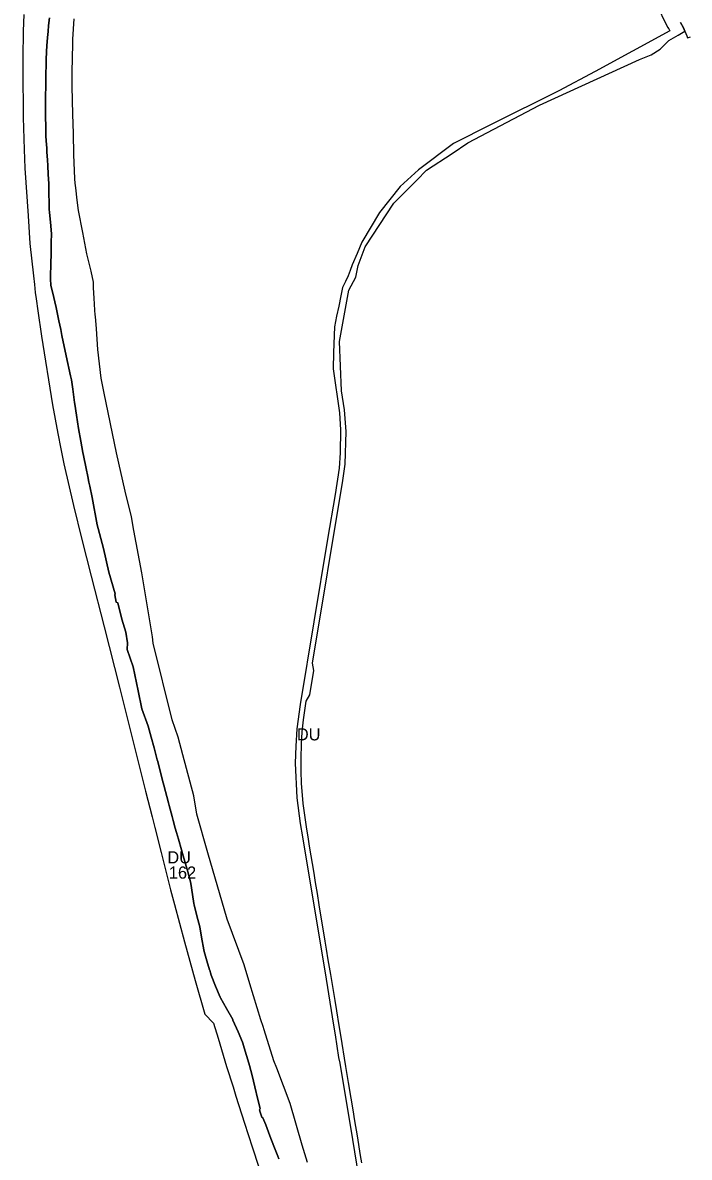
# Model space of a CAD drawing. Extents: x -521047 to -518054, y -1194945 to -1189555.
# Drawn here: x -520854 to -520307, y -1191621 to -1190690 of the extents above; entities that cross this region are included whole.
import ezdxf

# ---------------------------------------------------------------- set-up
doc = ezdxf.new("R2010")
doc.units = 0
for name, color, linetype in [('90310013', 7, 'Continuous'), ('90310023', 7, 'Continuous'), ('90320013', 7, 'Continuous'), ('ID_navrh', 7, 'Continuous')]:
    doc.layers.add(name, color=color, linetype=linetype)

msp = doc.modelspace()

# ---------------------------------------------------------------- linework, layer by layer
at = {"layer": '90310013'}
for points in [[(-520334, -1190674.28), (-520324.46, -1190693.89), (-520323.5, -1190695.35), (-520322.54, -1190696.8), (-520383.85, -1190730.39), (-520413.62, -1190746.07), (-520469.27, -1190773.73), (-520500.11, -1190789.41), (-520528.99, -1190810.95), (-520544.03, -1190824.72), (-520560.86, -1190845.88), (-520575.39, -1190870.36), (-520579.33, -1190879.67), (-520583.27, -1190888.97), (-520584.97, -1190893.45), (-520586.68, -1190897.92), (-520588.94, -1190902.65), (-520591.21, -1190907.38), (-520592.68, -1190914.39), (-520594.41, -1190922.81), (-520596.29, -1190931.07), (-520597.97, -1190939.69), (-520598.61, -1190960.68), (-520598.93, -1190974.08), (-520593.81, -1191010.23), (-520592.99, -1191024.28), (-520593.17, -1191043.04), (-520594.04, -1191055.69), (-520597.48, -1191077.12), (-520603.55, -1191113.81), (-520626.01, -1191249.41), (-520628.76, -1191269.45), (-520629.76, -1191283.58), (-520630.1, -1191297.74), (-520628.78, -1191326.02), (-520625.98, -1191347.07), (-520624.05, -1191357.94), (-520604.82, -1191474.76), (-520598.71, -1191512.42), (-520597.37, -1191520.53), (-520594.55, -1191539), (-520593.47, -1191543.67), (-520583.24, -1191606.18), (-520572.92, -1191668.76)], [(-520575.51, -1191625.38), (-520576.48, -1191619.53), (-520579.1, -1191603.39), (-520581.19, -1191591.03), (-520582.68, -1191582), (-520584.24, -1191572.29), (-520586.36, -1191559.62), (-520588.55, -1191546.35), (-520592.74, -1191520.81), (-520594.1, -1191512.73), (-520596.04, -1191500.86), (-520597.47, -1191492.24), (-520599.4, -1191480.74), (-520601.01, -1191470.86), (-520603, -1191458.86), (-520604.41, -1191450.26), (-520605.54, -1191443.5), (-520610.43, -1191413.76), (-520611.93, -1191404.62), (-520613.42, -1191395.5), (-520614.72, -1191387.87), (-520618.35, -1191365.76), (-520619.6, -1191358.04), (-520620.71, -1191351.68), (-520623.65, -1191330.68), (-520625.07, -1191313.94), (-520625.36, -1191304.16), (-520625.38, -1191293.53), (-520625.11, -1191281.97), (-520624.38, -1191271.96), (-520623.25, -1191261.94), (-520621.13, -1191246.77), (-520618.19, -1191241.45), (-520614.89, -1191221.55), (-520615.94, -1191215.64), (-520591.05, -1191065.64), (-520589.24, -1191052.36), (-520588.39, -1191025.58), (-520589.79, -1191007.77), (-520592.04, -1190992.31), (-520593.76, -1190951.86), (-520586.27, -1190909.59), (-520580.44, -1190899.06), (-520578.54, -1190889.51), (-520572.63, -1190874.12), (-520549.3, -1190838.28), (-520530.27, -1190819.39), (-520522.25, -1190811.26), (-520501.34, -1190797.6), (-520488.55, -1190788.82), (-520429.7, -1190757.81), (-520347.53, -1190720.51), (-520337.94, -1190716.53), (-520330.69, -1190711.95), (-520323.58, -1190704.71), (-520315.88, -1190700.41), (-520310.32, -1190697.3), (-520311.54, -1190694.38), (-520313.81, -1190690.05)]]:
    msp.add_lwpolyline(points, dxfattribs=at)
at = {"layer": '90310023'}
for points in [[(-520852.94, -1190683.51), (-520853.37, -1190697.08), (-520853.44, -1190702.35), (-520853.63, -1190713.88), (-520853.79, -1190723.11), (-520853.87, -1190735.1), (-520853.81, -1190743.83), (-520853.6, -1190752.22), (-520853.48, -1190767.88), (-520852.66, -1190794.34), (-520852.06, -1190809.58), (-520849.49, -1190848.58), (-520847.98, -1190871.46), (-520845.07, -1190897.78), (-520844.23, -1190905.1), (-520843.48, -1190911.63), (-520842.9, -1190916.64), (-520841.49, -1190926.47), (-520838.45, -1190947.47), (-520829.51, -1191003.76), (-520825.08, -1191027.11), (-520822.58, -1191039.85), (-520820.01, -1191052.05), (-520812.23, -1191086.24), (-520805.2, -1191114.16), (-520797.61, -1191144.17), (-520786.96, -1191185.86), (-520774.39, -1191235.28), (-520762.01, -1191284.51), (-520752.93, -1191320.48), (-520747.53, -1191341.72), (-520745.31, -1191350.43), (-520740.08, -1191370.95), (-520732.39, -1191401.49), (-520729.17, -1191413.61), (-520721.14, -1191444.12), (-520712.23, -1191475.88), (-520704.46, -1191503.52), (-520697.13, -1191510.79), (-520693.46, -1191523.23), (-520686.61, -1191546.52), (-520681.21, -1191563.06), (-520678.86, -1191570.86), (-520671.8, -1191593.01), (-520668.87, -1191602.22), (-520665.33, -1191613.04), (-520660.4, -1191628.12)], [(-520643.73, -1191622.06), (-520644.52, -1191620), (-520647.71, -1191611.67), (-520650.9, -1191603.35), (-520654.37, -1191594.38), (-520656.67, -1191588.4), (-520657.54, -1191587.89), (-520658.88, -1191583.95), (-520659.53, -1191582.02), (-520659, -1191580.96), (-520660.82, -1191573.42), (-520663.33, -1191563.05), (-520665.57, -1191553.76), (-520667.57, -1191545.47), (-520668.09, -1191543.82), (-520672, -1191531.21), (-520673.22, -1191527.27), (-520673.5, -1191526.37), (-520677.1, -1191518.04), (-520681.26, -1191508.41), (-520681.46, -1191507.94), (-520686.56, -1191498.88), (-520691.48, -1191490.13), (-520691.77, -1191489.43), (-520695.45, -1191480.44), (-520699.15, -1191471.42), (-520699.7, -1191469.55), (-520700.29, -1191467.53), (-520700.44, -1191467.02), (-520702.59, -1191459.74), (-520704.85, -1191452.06), (-520705.09, -1191450.73), (-520707.01, -1191440.35), (-520707.04, -1191440.19), (-520708.5, -1191432.23), (-520708.55, -1191432.06), (-520708.58, -1191431.92), (-520710.82, -1191422.94), (-520713.09, -1191413.86), (-520713.37, -1191412.72), (-520714.5, -1191405.34), (-520715.9, -1191396.27), (-520716.12, -1191394.83), (-520718.38, -1191386.7), (-520720.76, -1191378.14), (-520722.03, -1191373.58), (-520723.44, -1191368.78), (-520726.04, -1191360.01), (-520727.71, -1191354.35), (-520728.59, -1191350.94), (-520730.21, -1191344.64), (-520731.14, -1191341.3), (-520733.65, -1191332.34), (-520734.26, -1191330.16), (-520738.06, -1191315.61), (-520738.56, -1191313.65), (-520741, -1191304.12), (-520743.03, -1191296.2), (-520743.4, -1191294.83), (-520746.06, -1191284.98), (-520748.41, -1191276.25), (-520750.85, -1191267.23), (-520755.98, -1191253.01), (-520759.01, -1191238.19), (-520763.23, -1191218.65), (-520768, -1191204.35), (-520767.93, -1191199.01), (-520769.22, -1191190.15), (-520772.34, -1191179.58), (-520775.88, -1191166.14), (-520777.03, -1191165.48), (-520778.32, -1191159.41), (-520777.9, -1191158.6), (-520783.01, -1191140.89), (-520787.55, -1191121.39), (-520791.94, -1191104.99), (-520792.74, -1191102), (-520796.93, -1191079.59), (-520798.81, -1191070.46), (-520799.51, -1191067.05), (-520800.44, -1191062.53), (-520801.76, -1191055.91), (-520803.88, -1191045.24), (-520804.36, -1191042.81), (-520806.03, -1191033.62), (-520807.96, -1191023.01), (-520809.71, -1191012.14), (-520811.15, -1191003.13), (-520811.34, -1191001.73), (-520812.78, -1190990.94), (-520813.82, -1190983.19), (-520814.56, -1190979.91), (-520818.22, -1190963.51), (-520821.62, -1190946.91), (-520821.98, -1190945.15), (-520822.65, -1190941.82), (-520824.09, -1190934.71), (-520824.34, -1190933.44), (-520826.26, -1190923.93), (-520829.46, -1190910.89), (-520830.74, -1190905.71), (-520831.08, -1190900.46), (-520831.02, -1190897.74), (-520830.82, -1190888.52), (-520830.61, -1190878.92), (-520830.42, -1190870.43), (-520830.27, -1190863.43), (-520831.11, -1190853.75), (-520831.79, -1190846.02), (-520832.02, -1190843.31), (-520832.12, -1190838.18), (-520832.28, -1190829.94), (-520832.41, -1190823.17), (-520832.46, -1190822.22), (-520832.83, -1190814.81), (-520833.2, -1190807.31), (-520833.41, -1190803.07), (-520833.68, -1190799.5), (-520833.91, -1190796.45), (-520834.16, -1190793.02), (-520834.61, -1190787.07), (-520834.92, -1190782.92), (-520834.94, -1190780.45), (-520834.99, -1190774.65), (-520835.04, -1190768.27), (-520835.08, -1190762.76), (-520835.08, -1190762.45), (-520835.08, -1190762.16), (-520835.05, -1190756.12), (-520835.02, -1190749.26), (-520834.99, -1190743.76), (-520834.99, -1190742.61), (-520834.91, -1190737.42), (-520834.82, -1190731.68), (-520834.72, -1190725.53), (-520834.67, -1190722.46), (-520834.57, -1190720.65), (-520834.19, -1190713.84), (-520833.93, -1190709.32), (-520833.53, -1190702.3), (-520833.06, -1190697.52), (-520832.56, -1190692.51), (-520831.92, -1190686.11)]]:
    msp.add_lwpolyline(points, dxfattribs=at)
at = {"layer": '90320013'}
for points in [[(-520831.92, -1190686.11), (-520832.56, -1190692.51), (-520833.06, -1190697.52), (-520833.53, -1190702.3), (-520833.93, -1190709.32), (-520834.19, -1190713.84), (-520834.57, -1190720.65), (-520834.67, -1190722.46), (-520834.72, -1190725.53), (-520834.82, -1190731.68), (-520834.91, -1190737.42), (-520834.99, -1190742.61), (-520834.99, -1190743.76), (-520835.02, -1190749.26), (-520835.05, -1190756.12), (-520835.08, -1190762.16), (-520835.08, -1190762.45), (-520835.08, -1190762.76), (-520835.04, -1190768.27), (-520834.99, -1190774.65), (-520834.94, -1190780.45), (-520834.92, -1190782.92), (-520834.61, -1190787.07), (-520834.16, -1190793.02), (-520833.91, -1190796.45), (-520833.68, -1190799.5), (-520833.41, -1190803.07), (-520833.2, -1190807.31), (-520832.83, -1190814.81), (-520832.46, -1190822.22), (-520832.41, -1190823.17), (-520832.28, -1190829.94), (-520832.12, -1190838.18), (-520832.02, -1190843.31), (-520831.79, -1190846.02), (-520831.11, -1190853.75), (-520830.27, -1190863.43), (-520830.42, -1190870.43), (-520830.61, -1190878.92), (-520830.82, -1190888.52), (-520831.02, -1190897.74), (-520831.08, -1190900.46), (-520830.74, -1190905.71), (-520829.46, -1190910.89), (-520826.26, -1190923.93), (-520824.34, -1190933.44), (-520824.09, -1190934.71), (-520822.65, -1190941.82), (-520821.98, -1190945.15), (-520821.62, -1190946.91), (-520818.22, -1190963.51), (-520814.56, -1190979.91), (-520813.82, -1190983.19), (-520812.78, -1190990.94), (-520811.34, -1191001.73), (-520811.15, -1191003.13), (-520809.71, -1191012.14), (-520807.96, -1191023.01), (-520806.03, -1191033.62), (-520804.36, -1191042.81), (-520803.88, -1191045.24), (-520801.76, -1191055.91), (-520800.44, -1191062.53), (-520799.51, -1191067.05), (-520798.81, -1191070.46), (-520796.93, -1191079.59), (-520792.74, -1191102), (-520791.94, -1191104.99), (-520787.55, -1191121.39), (-520783.01, -1191140.89), (-520777.9, -1191158.6), (-520778.32, -1191159.41), (-520777.03, -1191165.48), (-520775.88, -1191166.14), (-520772.34, -1191179.58), (-520769.22, -1191190.15), (-520767.93, -1191199.01), (-520768, -1191204.35), (-520763.23, -1191218.65), (-520759.01, -1191238.19), (-520755.98, -1191253.01), (-520750.85, -1191267.23), (-520748.41, -1191276.25), (-520746.06, -1191284.98), (-520743.4, -1191294.83), (-520743.03, -1191296.2), (-520741, -1191304.12), (-520738.56, -1191313.65), (-520738.06, -1191315.61), (-520734.26, -1191330.16), (-520733.65, -1191332.34), (-520731.14, -1191341.3), (-520730.21, -1191344.64), (-520728.59, -1191350.94), (-520727.71, -1191354.35), (-520726.04, -1191360.01), (-520723.44, -1191368.78), (-520722.03, -1191373.58), (-520720.76, -1191378.14), (-520718.38, -1191386.7), (-520716.12, -1191394.83), (-520715.9, -1191396.27), (-520714.5, -1191405.34), (-520713.37, -1191412.72), (-520713.09, -1191413.86), (-520710.82, -1191422.94), (-520708.58, -1191431.92), (-520708.55, -1191432.06), (-520708.5, -1191432.23), (-520707.04, -1191440.19), (-520707.01, -1191440.35), (-520705.09, -1191450.73), (-520704.85, -1191452.06), (-520702.59, -1191459.74), (-520700.44, -1191467.02), (-520700.29, -1191467.53), (-520699.7, -1191469.55), (-520699.15, -1191471.42), (-520695.45, -1191480.44), (-520691.77, -1191489.43), (-520691.48, -1191490.13), (-520686.56, -1191498.88), (-520681.46, -1191507.94), (-520681.26, -1191508.41), (-520677.1, -1191518.04), (-520673.5, -1191526.37), (-520673.22, -1191527.27), (-520672, -1191531.21), (-520668.09, -1191543.82), (-520667.57, -1191545.47), (-520665.57, -1191553.76), (-520663.33, -1191563.05), (-520660.82, -1191573.42), (-520659, -1191580.96), (-520659.53, -1191582.02), (-520658.88, -1191583.95), (-520657.54, -1191587.89), (-520656.67, -1191588.4), (-520654.37, -1191594.38), (-520650.9, -1191603.35), (-520647.71, -1191611.67), (-520644.52, -1191620), (-520643.73, -1191622.06)], [(-520620.11, -1191625.25), (-520624.44, -1191610.86), (-520634.42, -1191576.76), (-520645.29, -1191547.71), (-520647.74, -1191541.74), (-520655.62, -1191516.43), (-520656.53, -1191513.73), (-520658.4, -1191508.21), (-520667.4, -1191478.56), (-520672.11, -1191463.11), (-520686.01, -1191425.6), (-520701.83, -1191371.04), (-520710.85, -1191339.33), (-520713.4, -1191324.5), (-520722.32, -1191290.79), (-520726.33, -1191276.25), (-520728.77, -1191269.08), (-520731.29, -1191262.08), (-520746.79, -1191199.07), (-520747.26, -1191194.03), (-520756.19, -1191141.57), (-520762.68, -1191106.73), (-520764.59, -1191095.68), (-520769.65, -1191074.63), (-520776.73, -1191043.11), (-520787.08, -1190994.15), (-520789.33, -1190981.89), (-520792.16, -1190958.16), (-520793.22, -1190941.3), (-520794.11, -1190931.35), (-520794.23, -1190929.98), (-520794.58, -1190926.05), (-520795.25, -1190916.18), (-520795.63, -1190907.7), (-520795.84, -1190903.04), (-520796.83, -1190897.77), (-520797.4, -1190895.45), (-520797.73, -1190894.1), (-520801.14, -1190879.93), (-520804.62, -1190862.21), (-520808.06, -1190844.37), (-520809.15, -1190835.67), (-520810.29, -1190825.6), (-520810.72, -1190821.89), (-520810.92, -1190818.26), (-520811.77, -1190798.26), (-520812.06, -1190781.24), (-520812.68, -1190765.38), (-520813.33, -1190742.53), (-520813.31, -1190730.65), (-520812.83, -1190707.72), (-520812.74, -1190703.8), (-520811.58, -1190686.99)], [(-520313.81, -1190690.05), (-520311.54, -1190694.38), (-520310.32, -1190697.3), (-520308.79, -1190700.97), (-520308.05, -1190702.75), (-520305.81, -1190701.95)]]:
    msp.add_lwpolyline(points, dxfattribs=at)

# ---------------------------------------------------------------- texts
at = {"layer": '90310013'}
msp.add_text('DU', height=10, rotation=360, dxfattribs=at).set_placement((-520628.77, -1191278.95))
at = {"layer": '90310023'}
msp.add_text('DU', height=10, rotation=0, dxfattribs=at).set_placement((-520735.07, -1191379.83))
at = {"layer": 'ID_navrh'}
msp.add_text('162', height=10, rotation=0, dxfattribs=at).set_placement((-520733.83, -1191392.35))

doc.saveas('drawing.dxf')
